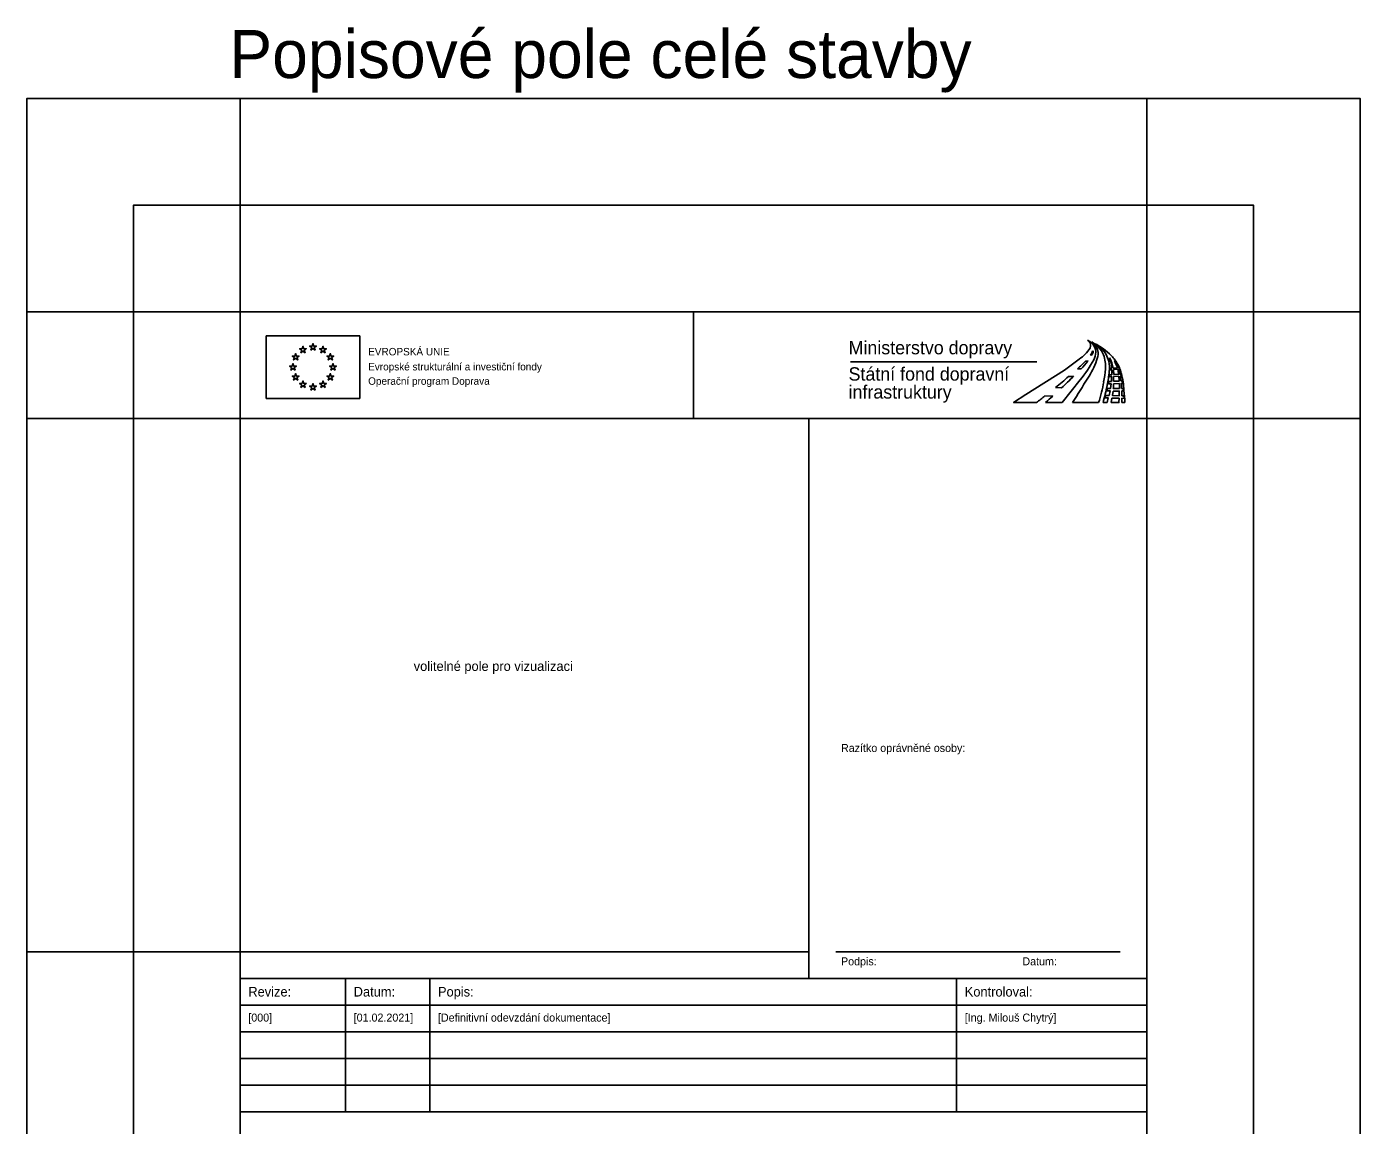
# Model space of a CAD drawing. Extents: x -27 to 48, y -2 to 33.
# Drawn here: x -27 to -2, y 12.45 to 33.05 of the extents above; entities that cross this region are included whole.
import ezdxf

# ---------------------------------------------------------------- set-up
doc = ezdxf.new("R2010")
doc.units = 0
for name, color, linetype in [('Default', 7, 'Continuous'), ('Rozpiska_Logo', 7, 'Continuous'), ('Rozpiska_pola_3', 7, 'Continuous'), ('Rozpiska_pole_1', 7, 'Continuous'), ('Rozpiska_pole_2', 7, 'Continuous'), ('Rozpiska_pole_4', 7, 'Continuous')]:
    doc.layers.add(name, color=color, linetype=linetype)

msp = doc.modelspace()

# ---------------------------------------------------------------- linework, layer by layer
at = {"layer": 'Default'}
for p, q in [((-23, 27.7), (-23, 31.7)), ((-6, 27.7), (-6, 31.7)), ((-23, 27.7), (-27, 27.7)), ((-14.5, 27.7), (-14.5, 25.7)), ((-6, 27.7), (-2, 27.7)), ((-27, 25.7), (-2, 25.7)), ((-12.335, 15.2), (-12.335, 25.7)), ((-27, 15.7), (-12.335, 15.7))]:
    msp.add_line(p, q, dxfattribs=at)
for points in [[(-27, -2), (-2, -2), (-2, 31.7), (-27, 31.7)], [(-25, 0), (-4, 0), (-4, 29.7), (-25, 29.7)]]:
    msp.add_lwpolyline(points, close=True, dxfattribs=at)
at = {"layer": 'Rozpiska_Logo'}
msp.add_line((-11.558, 26.762), (-8.061, 26.762), dxfattribs=at)
for points in [[(-22.51, 27.249), (-20.757, 27.249), (-20.756, 26.08), (-22.51, 26.08), (-22.51, 27.249)], [(-21.884, 27.01), (-21.836, 27.01), (-21.821, 27.056), (-21.806, 27.01), (-21.758, 27.01), (-21.797, 26.982), (-21.782, 26.936), (-21.821, 26.964), (-21.86, 26.936), (-21.845, 26.982), (-21.884, 27.01)], [(-21.845, 26.982), (-21.86, 26.936), (-21.821, 26.964), (-21.782, 26.936), (-21.797, 26.982), (-21.758, 27.01), (-21.806, 27.01), (-21.821, 27.056), (-21.836, 27.01), (-21.884, 27.01), (-21.845, 26.982)], [(-21.696, 27.06), (-21.648, 27.06), (-21.633, 27.106), (-21.618, 27.06), (-21.57, 27.06), (-21.609, 27.032), (-21.594, 26.986), (-21.633, 27.015), (-21.672, 26.986), (-21.657, 27.032), (-21.696, 27.06)], [(-21.657, 27.032), (-21.672, 26.986), (-21.633, 27.015), (-21.594, 26.986), (-21.609, 27.032), (-21.57, 27.06), (-21.618, 27.06), (-21.633, 27.106), (-21.648, 27.06), (-21.696, 27.06), (-21.657, 27.032)], [(-21.509, 27.01), (-21.46, 27.01), (-21.446, 27.056), (-21.431, 27.01), (-21.382, 27.01), (-21.421, 26.982), (-21.407, 26.936), (-21.446, 26.964), (-21.485, 26.936), (-21.47, 26.982), (-21.509, 27.01)], [(-21.47, 26.982), (-21.485, 26.936), (-21.446, 26.964), (-21.407, 26.936), (-21.421, 26.982), (-21.382, 27.01), (-21.431, 27.01), (-21.446, 27.056), (-21.46, 27.01), (-21.509, 27.01), (-21.47, 26.982)], [(-22.021, 26.873), (-21.973, 26.873), (-21.958, 26.919), (-21.943, 26.873), (-21.895, 26.873), (-21.934, 26.844), (-21.919, 26.799), (-21.958, 26.827), (-21.997, 26.799), (-21.982, 26.844), (-22.021, 26.873)], [(-21.982, 26.844), (-21.997, 26.799), (-21.958, 26.827), (-21.919, 26.799), (-21.934, 26.844), (-21.895, 26.873), (-21.943, 26.873), (-21.958, 26.919), (-21.973, 26.873), (-22.021, 26.873), (-21.982, 26.844)], [(-21.371, 26.873), (-21.323, 26.873), (-21.308, 26.919), (-21.293, 26.873), (-21.245, 26.873), (-21.284, 26.845), (-21.269, 26.799), (-21.308, 26.827), (-21.347, 26.799), (-21.332, 26.845), (-21.371, 26.873)], [(-21.332, 26.845), (-21.347, 26.799), (-21.308, 26.827), (-21.269, 26.799), (-21.284, 26.845), (-21.245, 26.873), (-21.293, 26.873), (-21.308, 26.919), (-21.323, 26.873), (-21.371, 26.873), (-21.332, 26.845)], [(-8.069, 26), (-8.499, 26), (-8.268, 26.151), (-7.548, 26.61), (-7.268, 26.815)], [(-7.108, 26.777), (-7.108, 26.777), (-7.153, 26.778)], [(-7.058, 26.889), (-7.038, 26.889)], [(-7.007, 26.964), (-7.007, 26.964), (-7.023, 26.964)], [(-22.072, 26.685), (-22.023, 26.685), (-22.008, 26.731), (-21.994, 26.685), (-21.945, 26.685), (-21.984, 26.657), (-21.969, 26.611), (-22.008, 26.639), (-22.047, 26.611), (-22.033, 26.657), (-22.072, 26.685)], [(-22.033, 26.657), (-22.047, 26.611), (-22.008, 26.639), (-21.969, 26.611), (-21.984, 26.657), (-21.945, 26.685), (-21.994, 26.685), (-22.008, 26.731), (-22.023, 26.685), (-22.072, 26.685), (-22.033, 26.657)], [(-22.021, 26.497), (-21.973, 26.497), (-21.958, 26.543), (-21.943, 26.497), (-21.895, 26.497), (-21.934, 26.469), (-21.919, 26.423), (-21.958, 26.452), (-21.997, 26.423), (-21.982, 26.469), (-22.021, 26.497)], [(-21.982, 26.469), (-21.997, 26.423), (-21.958, 26.452), (-21.919, 26.423), (-21.934, 26.469), (-21.895, 26.497), (-21.943, 26.497), (-21.958, 26.543), (-21.973, 26.497), (-22.021, 26.497), (-21.982, 26.469)], [(-21.371, 26.498), (-21.323, 26.498), (-21.308, 26.543), (-21.293, 26.498), (-21.245, 26.498), (-21.284, 26.469), (-21.269, 26.423), (-21.308, 26.452), (-21.347, 26.423), (-21.332, 26.469), (-21.371, 26.498)], [(-21.332, 26.469), (-21.347, 26.423), (-21.308, 26.452), (-21.269, 26.423), (-21.284, 26.469), (-21.245, 26.498), (-21.293, 26.498), (-21.308, 26.543), (-21.323, 26.498), (-21.371, 26.498), (-21.332, 26.469)], [(-21.321, 26.685), (-21.273, 26.685), (-21.258, 26.731), (-21.243, 26.685), (-21.195, 26.685), (-21.234, 26.657), (-21.219, 26.611), (-21.258, 26.639), (-21.297, 26.611), (-21.282, 26.657), (-21.321, 26.685)], [(-21.282, 26.657), (-21.297, 26.611), (-21.258, 26.639), (-21.219, 26.611), (-21.234, 26.657), (-21.195, 26.685), (-21.243, 26.685), (-21.258, 26.731), (-21.273, 26.685), (-21.321, 26.685), (-21.282, 26.657)], [(-7.302, 26.632), (-7.236, 26.632)], [(-6.659, 26.523), (-6.699, 26.52), (-6.704, 26.485), (-6.661, 26.487)], [(-6.658, 26.647), (-6.691, 26.645), (-6.692, 26.614), (-6.659, 26.617)], [(-6.556, 26.653), (-6.636, 26.648)], [(-6.548, 26.626), (-6.629, 26.619)], [(-6.621, 26.525), (-6.53, 26.53)], [(-6.529, 26.628), (-6.516, 26.628), (-6.526, 26.655), (-6.541, 26.654)], [(-6.5, 26.494), (-6.482, 26.495), (-6.49, 26.532), (-6.507, 26.531)], [(-21.884, 26.36), (-21.836, 26.36), (-21.821, 26.406), (-21.806, 26.36), (-21.758, 26.36), (-21.797, 26.332), (-21.782, 26.286), (-21.821, 26.314), (-21.86, 26.286), (-21.845, 26.332), (-21.884, 26.36)], [(-21.845, 26.332), (-21.86, 26.286), (-21.821, 26.314), (-21.782, 26.286), (-21.797, 26.332), (-21.758, 26.36), (-21.806, 26.36), (-21.821, 26.406), (-21.836, 26.36), (-21.884, 26.36), (-21.845, 26.332)], [(-21.696, 26.31), (-21.648, 26.31), (-21.633, 26.356), (-21.618, 26.31), (-21.57, 26.31), (-21.609, 26.282), (-21.594, 26.236), (-21.633, 26.264), (-21.672, 26.236), (-21.657, 26.282), (-21.696, 26.31)], [(-21.657, 26.282), (-21.672, 26.236), (-21.633, 26.264), (-21.594, 26.236), (-21.609, 26.282), (-21.57, 26.31), (-21.618, 26.31), (-21.633, 26.356), (-21.648, 26.31), (-21.696, 26.31), (-21.657, 26.282)], [(-21.509, 26.36), (-21.46, 26.36), (-21.445, 26.406), (-21.431, 26.36), (-21.382, 26.36), (-21.421, 26.332), (-21.406, 26.286), (-21.445, 26.314), (-21.484, 26.286), (-21.47, 26.332), (-21.509, 26.36)], [(-21.47, 26.332), (-21.484, 26.286), (-21.445, 26.314), (-21.406, 26.286), (-21.421, 26.332), (-21.382, 26.36), (-21.431, 26.36), (-21.445, 26.406), (-21.46, 26.36), (-21.509, 26.36), (-21.47, 26.332)], [(-7.251, 26.424), (-7.592, 26), (-7.899, 26)], [(-7.714, 26.282), (-7.6, 26.276)], [(-7.376, 26.491), (-7.376, 26.491), (-7.469, 26.491)], [(-6.667, 26.398), (-6.717, 26.396), (-6.723, 26.353), (-6.672, 26.354), (-6.684, 26.263), (-6.739, 26.263), (-6.75, 26.222), (-6.692, 26.221), (-6.71, 26.135), (-6.775, 26.136), (-6.782, 26.089), (-6.725, 26.088), (-6.745, 26)], [(-6.631, 26.263), (-6.516, 26.263)], [(-6.516, 26.356), (-6.628, 26.354)], [(-6.625, 26.4), (-6.521, 26.404)], [(-6.526, 26.493), (-6.624, 26.489)], [(-6.482, 26.357), (-6.457, 26.357), (-6.464, 26.406), (-6.489, 26.405)], [(-6.473, 26.218), (-6.44, 26.218), (-6.446, 26.263), (-6.476, 26.263)], [(-7.765, 26.121), (-7.765, 26.121), (-7.912, 26.126)], [(-6.635, 26.217), (-6.645, 26.133), (-6.52, 26.13), (-6.518, 26.216), (-6.635, 26.217)], [(-6.468, 26), (-6.469, 26.081), (-6.429, 26.08), (-6.434, 26.128), (-6.47, 26.129)], [(-6.907, 26), (-7.395, 26)], [(-6.823, 26), (-6.745, 26)], [(-6.673, 26), (-6.627, 26)], [(-6.468, 26), (-6.412, 26)]]:
    msp.add_lwpolyline(points, dxfattribs=at)
msp.add_lwpolyline([(-6.673, 26), (-6.656, 26.083), (-6.522, 26.083), (-6.525, 25.999)], close=True, dxfattribs=at)
for centre, radius, start, end in [((-7.727, 27.467), 0.797, 305.1305, 325.9532), ((-7.171, 27.072), 0.116, 333.7821, 60.3253), ((-7.236, 26.911), 0.289, 35.1291, 64.7751), ((-7.341, 26.616), 0.605, 44.354, 59.6129), ((-7.21, 26.894), 0.299, 8.8325, 54.3171), ((-7.182, 26.949), 0.223, 358.3059, 35.1291), ((-16.824, 14.325), 16.135, 51.8348, 52.3632), ((-7.426, 26.192), 1.018, 55.8173, 63.4675), ((-7.227, 26.731), 0.443, 21.6804, 44.0388), ((-7.292, 26.309), 0.847, 45.7577, 58.8317), ((-7.148, 26.684), 0.44, 29.5083, 48.0349), ((-8.972, 28.492), 2.499, 311.9225, 316.7053), ((-9.307, 28.076), 2.637, 321.2414, 331.1155), ((-10.757, 29.883), 4.793, 317.2846, 319.5966), ((-8.441, 27.344), 1.598, 326.3997, 339.6645), ((-7.177, 26.991), 0.156, 319.6022, 350.325), ((-7.171, 26.988), 0.166, 323.7342, 351.8118), ((-7.271, 26.952), 0.312, 331.1155, 358.3059), ((-7.373, 26.948), 0.459, 339.6691, 359.0927), ((-7.372, 26.682), 0.596, 354.8309, 20.9259), ((-7.14, 26.684), 0.433, 12.5999, 30.087), ((-7.172, 26.659), 0.47, 350.7277, 14.6627), ((-7.073, 26.594), 0.441, 6.9884, 33.3949), ((-7.229, 26.608), 0.572, 3.8889, 23.6112), ((-7.288, 26.301), 0.85, 32.4145, 46.3283), ((-7.051, 26.477), 0.539, 19.1508, 35.05), ((-7.708, 26.274), 1.213, 18.2045, 25.0006), ((-7.099, 26.403), 0.636, 13.4543, 33.7828), ((-8.451, 26.736), 1.676, 348.0644, 356.2998), ((-8.742, 26.744), 2.04, 348.131, 355.4957), ((-7.822, 26.567), 1.164, 357.822, 2.4688), ((-7.578, 26.493), 0.957, 1.9262, 7.6145), ((-7.338, 26.427), 0.815, 7.2316, 14.102), ((-7.11, 26.443), 0.61, 8.3249, 17.6578), ((-8.054, 26.146), 1.625, 2.7985, 14.4251), ((-12.762, 32.429), 7.955, 309.3914, 311.7102), ((-11.427, 30.473), 5.68, 312.3671, 315.4937), ((-47.272, 51.084), 47.111, 327.8282, 328.4861), ((-9.615, 26.874), 2.846, 342.1151, 350.2059), ((-9.968, 26.929), 3.279, 343.5415, 349.3721), ((-4.798, 26.321), 1.871, 174.904, 177.6286), ((-7.169, 26.33), 0.541, 352.9784, 2.6252), ((-11.852, 26.5), 5.228, 358.9091, 359.8809), ((-8.463, 26.337), 1.943, 1.988, 4.6084), ((-7.147, 26.314), 0.633, 355.4573, 3.8566), ((-6.878, 26.405), 0.388, 0.0904, 13.2769), ((-7.546, 26.238), 1.071, 1.3852, 6.3824), ((-5.893, 23.462), 3.342, 127.1682, 130.6153), ((-6.049, 24.106), 2.647, 130.4231, 134.3309), ((-10.411, 26.048), 3.942, 1.1818, 2.4809), ((-9.71, 25.842), 3.301, 2.7322, 6.6695)]:
    msp.add_arc(centre, radius, start, end, dxfattribs=at)
at = {"layer": 'Rozpiska_pola_3'}
msp.add_line((-11.835, 15.7), (-6.5, 15.7), dxfattribs=at)
at = {"layer": 'Rozpiska_pole_1'}
msp.add_lwpolyline([(-23, 27.7), (-6, 27.7), (-6, 1.7), (-23, 1.7)], close=True, dxfattribs=at)
at = {"layer": 'Rozpiska_pole_2'}
msp.add_lwpolyline([(-23, 25.7), (-12.335, 25.7), (-12.335, 15.7), (-23, 15.7)], close=True, dxfattribs=at)
at = {"layer": 'Rozpiska_pole_4'}
for p, q in [((-21.025, 12.7), (-21.025, 15.2)), ((-19.445, 12.7), (-19.445, 15.2)), ((-9.57, 12.7), (-9.57, 15.2)), ((-23, 14.7), (-6, 14.7)), ((-23, 14.2), (-6, 14.2)), ((-23, 13.7), (-6, 13.7)), ((-23, 13.2), (-6, 13.2))]:
    msp.add_line(p, q, dxfattribs=at)
msp.add_lwpolyline([(-23, 15.2), (-6, 15.2), (-6, 12.7), (-23, 12.7)], close=True, dxfattribs=at)

# ---------------------------------------------------------------- texts
at = {"layer": 'Default'}
for s, height, p in [('Popisové pole celé stavby', 0.9, (-23.201, 32.085)), ('volitelné pole pro vizualizaci', 0.17997, (-19.745, 20.969))]:
    msp.add_text(s, height=height, dxfattribs=at).set_placement(p)
at = {"layer": 'Rozpiska_Logo'}
for s, height, p in [('EVROPSKÁ UNIE', 0.14, (-20.599, 26.885)), ('Ministerstvo dopravy', 0.25, (-11.593, 26.905)), ('Evropské strukturální a investiční fondy', 0.14, (-20.599, 26.603)), ('Státní fond dopravní', 0.25, (-11.593, 26.412)), ('Operační program Doprava', 0.14, (-20.599, 26.334)), ('infrastruktury', 0.25, (-11.593, 26.075))]:
    msp.add_text(s, height=height, rotation=0.0062, dxfattribs=at).set_placement(p)
at = {"layer": 'Rozpiska_pola_3'}
for s, p in [('Razítko oprávněné osoby:', (-11.735, 19.45)), ('Podpis:', (-11.735, 15.45)), ('Datum:', (-8.335, 15.45))]:
    msp.add_text(s, height=0.15, dxfattribs=at).set_placement(p)
at = {"layer": 'Rozpiska_pole_4'}
for s, height, p in [('Revize:', 0.18, (-22.845, 14.865)), ('Datum:', 0.18, (-20.87, 14.865)), ('Popis:', 0.18, (-19.29, 14.865)), ('Kontroloval:', 0.18, (-9.415, 14.865)), ('[000]', 0.15, (-22.845, 14.395)), ('[01.02.2021]', 0.15, (-20.87, 14.395)), ('[Definitivní odevzdání dokumentace]', 0.15, (-19.29, 14.395)), ('[Ing. Milouš Chytrý]', 0.15, (-9.415, 14.395))]:
    msp.add_text(s, height=height, dxfattribs=at).set_placement(p)

doc.saveas('drawing.dxf')
